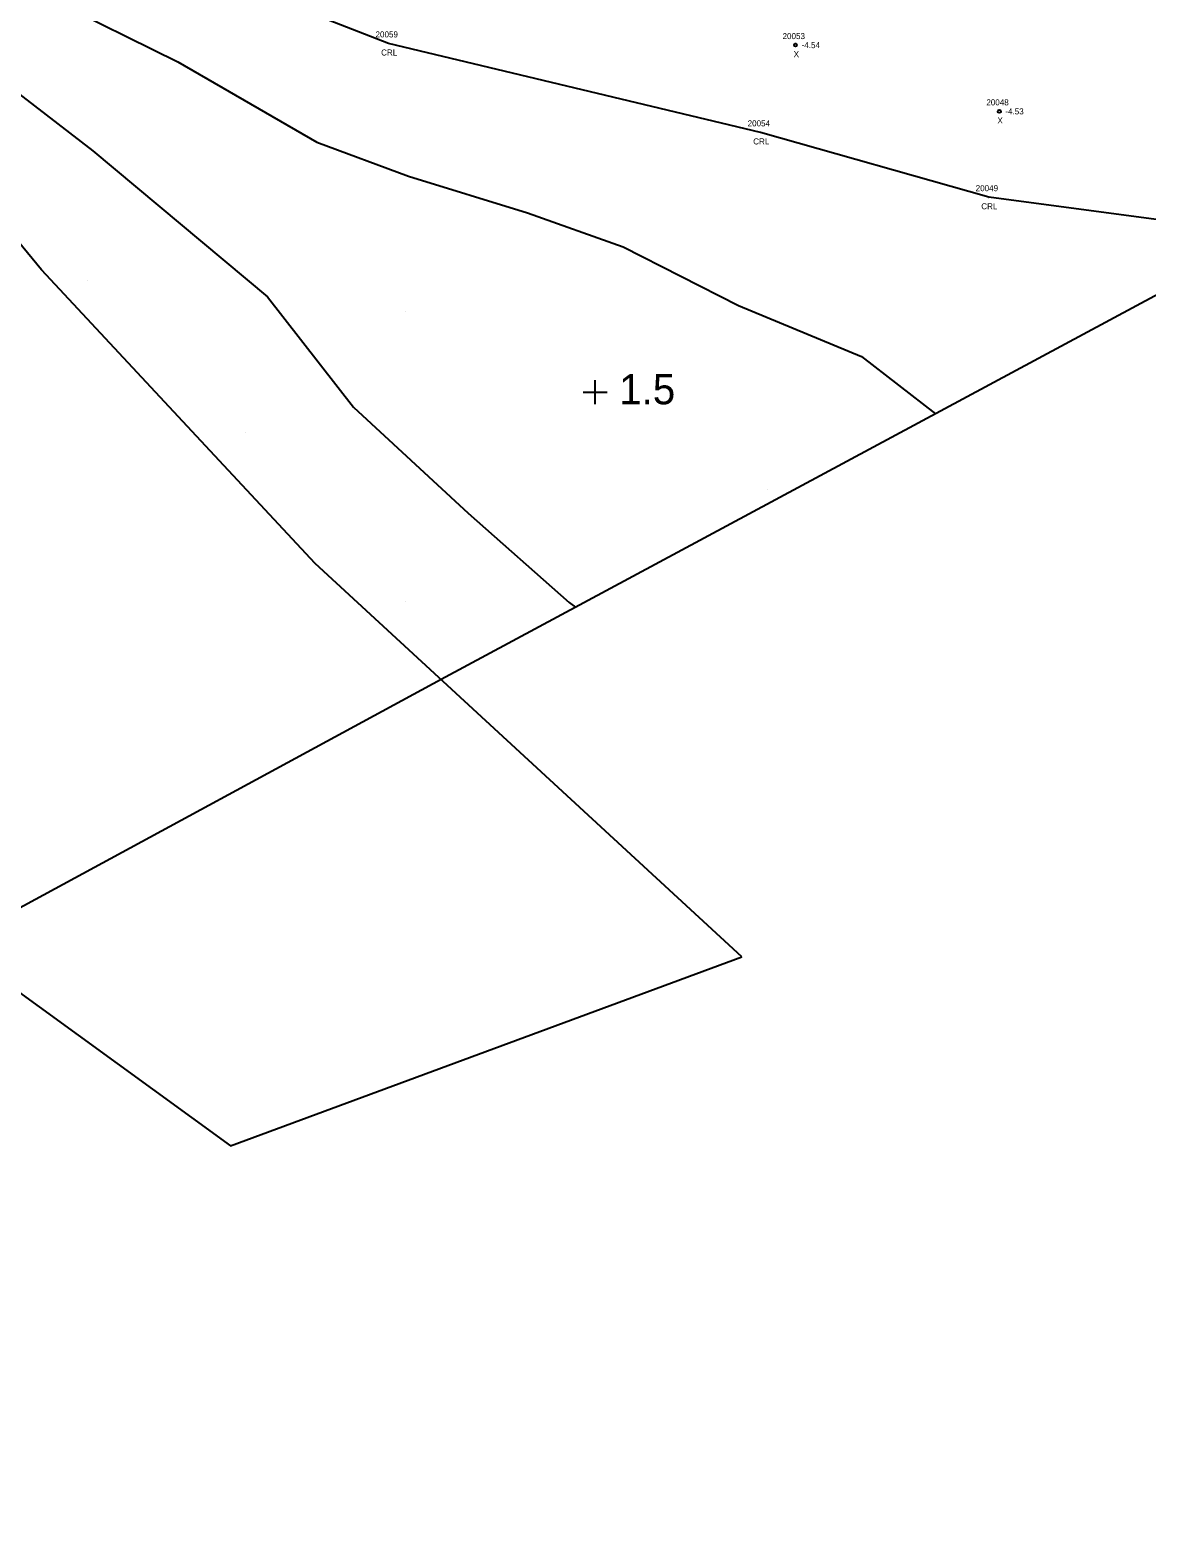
# Model space of a CAD drawing. Extents: x 2316231 to 2323598, y 363169 to 371906.
# Drawn here: x 2322369.6 to 2322554.9, y 368495.5 to 368745.7 of the extents above; entities that cross this region are included whole.
import ezdxf

# ---------------------------------------------------------------- set-up
doc = ezdxf.new("R2010")
doc.units = 0
for name, color, linetype in [('RD_DTM_BkLn1', 7, 'Continuous'), ('RD_DTM_Holes', 7, 'Continuous'), ('RD_DTM_Spot', 7, 'Continuous'), ('RD_DTM_TinHull', 7, 'Continuous'), ('RD_DTM_Void', 7, 'Continuous'), ('RD_EX_H2O', 7, 'Continuous'), ('RD_EX_H2O_txCode', 7, 'Continuous'), ('RD_Sketch8', 7, 'Continuous'), ('RD_SMD_Locator', 7, 'Continuous')]:
    doc.layers.add(name, color=color, linetype=linetype)

msp = doc.modelspace()

# ---------------------------------------------------------------- linework, layer by layer
at = {"layer": 'RD_DTM_BkLn1'}
for points in [[(2322328.92, 368765.028), (2322345.061, 368752.566), (2322379.986, 368725.661), (2322408.987, 368701.448), (2322423.259, 368683.143), (2322442.285, 368665.547), (2322459.045, 368650.707), (2322460.096, 368649.929)], [(2322372.996, 368750.87), (2322394.081, 368740.422), (2322417.172, 368727.113), (2322432.384, 368721.428), (2322452.124, 368715.347), (2322468.018, 368709.732), (2322487.14, 368700.017), (2322507.581, 368691.512), (2322519.856, 368682.037)]]:
    msp.add_lwpolyline(points, dxfattribs=at)
at = {"layer": 'RD_DTM_Holes'}
for points in [[(2322230.1, 368780.47), (2322278.66, 368734.155), (2322325.157, 368658.765), (2322313.947, 368625.047), (2322402.835, 368560.546), (2322487.679, 368591.9)], [(2322487.679, 368591.9), (2322416.897, 368657.169), (2322371.435, 368705.89), (2322322.556, 368765.239)]]:
    msp.add_lwpolyline(points, dxfattribs=at)
at = {"layer": 'RD_DTM_Spot'}
for p, q in [((2322379.101, 368704.077), (2322379.101, 368704.077)), ((2322431.897, 368698.985), (2322431.897, 368698.985)), ((2322463.341, 368685.602), (2322463.341, 368685.602)), ((2322405.277, 368678.998), (2322405.277, 368678.998)), ((2322491.921, 368669.389), (2322491.921, 368669.389)), ((2322431.942, 368650.861), (2322431.942, 368650.861))]:
    msp.add_line(p, q, dxfattribs=at)
at = {"layer": 'RD_DTM_TinHull'}
msp.add_lwpolyline([(2322749.057, 368805.183), (2322437.788, 368637.943), (2322185.484, 368501.144), (2321988.712, 368397.613), (2321906.574, 368261.806), (2321814.258, 368125.896), (2321753.197, 367969.571), (2321734.081, 367792.897), (2321812.341, 367285.803), (2321826.603, 366879.552), (2321787.983, 366568.052), (2321665.825, 366287.064), (2321428.475, 366067.062), (2321222.139, 365846.682), (2320971.939, 365770.635), (2320807.161, 365571.8), (2320809.363, 365353.877), (2320991.706, 364942.038)], dxfattribs=at)
at = {"layer": 'RD_DTM_Void'}
for p, q in [((2322463.341, 368683.602), (2322463.341, 368687.602)), ((2322461.341, 368685.602), (2322465.341, 368685.602))]:
    msp.add_line(p, q, dxfattribs=at)
at = {"layer": 'RD_EX_H2O'}
msp.add_lwpolyline([(2322824.245, 368500.388), (2322754.031, 368575.627), (2322718.665, 368602.203), (2322686.185, 368627.498), (2322647.263, 368669.146), (2322610.995, 368691.679), (2322563.913, 368713.274), (2322528.661, 368717.956), (2322490.81, 368728.714), (2322429.051, 368743.471), (2322384.251, 368760.961), (2322329.268, 368800.83), (2322290.811, 368833.671), (2322223.413, 368855.898)], dxfattribs=at)
at = {"layer": 'RD_SMD_Locator'}
for centre, radius in [((2322429.051, 368743.471), 0.001), ((2322496.611, 368743.191), 0.25), ((2322530.429, 368732.201), 0.25), ((2322490.81, 368728.714), 0.001), ((2322528.661, 368717.956), 0.001)]:
    msp.add_circle(centre, radius, dxfattribs=at)

# ---------------------------------------------------------------- texts
at = {"layer": 'RD_DTM_Void'}
msp.add_text('1.5', height=5, dxfattribs=at).set_placement((2322467.341, 368683.602))
at = {"layer": 'RD_EX_H2O_txCode'}
for s, p in [('20059', (2322426.893, 368744.471)), ('CRL', (2322427.822, 368741.471)), ('20054', (2322488.653, 368729.714)), ('CRL', (2322489.582, 368726.714)), ('20049', (2322526.504, 368718.956)), ('CRL', (2322527.433, 368715.956))]:
    msp.add_text(s, height=1, dxfattribs=at).set_placement(p)
at = {"layer": 'RD_Sketch8'}
for s, p in [('20053', (2322494.454, 368744.191)), ('X', (2322496.296, 368741.191)), ('-4.54', (2322497.611, 368742.691)), ('20048', (2322528.271, 368733.201)), ('-4.53', (2322531.429, 368731.701)), ('X', (2322530.114, 368730.201))]:
    msp.add_text(s, height=1, dxfattribs=at).set_placement(p)

doc.saveas('drawing.dxf')
